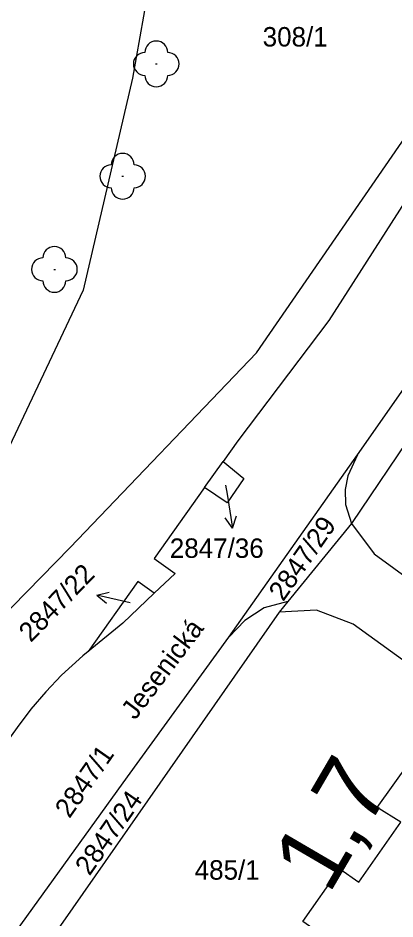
# Model space of a CAD drawing. Extents: x -558358 to -557517, y -1073786 to -1073189.
# Drawn here: x -558051.3 to -558018.3, y -1073345.8 to -1073267 of the extents above; entities that cross this region are included whole.
import ezdxf

# ---------------------------------------------------------------- set-up
doc = ezdxf.new("R2010")
doc.units = 0
for name, color, linetype in [('Drobná stavba - strom', 7, 'Continuous'), ('Hranice parcel', 7, 'Continuous'), ('Návěst místo trati', 7, 'Continuous'), ('Parcelní čísla', 7, 'Continuous'), ('Pop  PČ popisy', 7, 'Continuous'), ('Svazek obcí údolí Desné', 7, 'Continuous')]:
    doc.layers.add(name, color=color, linetype=linetype)

msp = doc.modelspace()

# ---------------------------------------------------------------- linework, layer by layer
at = {"layer": 'Drobná stavba - strom'}
for p, q in [((-558039.22, -1073271.013), (-558039.078, -1073271.013)), ((-558042.161, -1073280.838), (-558042.019, -1073280.838)), ((-558048.133, -1073288.982), (-558047.991, -1073288.982))]:
    msp.add_line(p, q, dxfattribs=at)
for centre, start, end in [((-558039.16, -1073270.011), 0, 180), ((-558040.16, -1073271.011), 90, 270), ((-558038.16, -1073271.011), 270, 90), ((-558039.16, -1073272.011), 180, 0), ((-558042.101, -1073279.836), 0, 180), ((-558043.101, -1073280.836), 90, 270), ((-558041.101, -1073280.836), 270, 90), ((-558042.101, -1073281.836), 180, 0), ((-558048.073, -1073287.98), 0, 180), ((-558049.073, -1073288.98), 90, 270), ((-558047.073, -1073288.98), 270, 90), ((-558048.073, -1073289.98), 180, 0)]:
    msp.add_arc(centre, 1, start, end, dxfattribs=at)
at = {"layer": 'Hranice parcel'}
for p, q in [((-557994.86, -1073270.9), (-558022.09, -1073311.21)), ((-558032.81, -1073321.13), (-558021.55, -1073305.19)), ((-558034.93, -1073308.06), (-558033.31, -1073305.78)), ((-558033.31, -1073305.78), (-558031.49, -1073307.27)), ((-558031.49, -1073307.27), (-558032.97, -1073309.39)), ((-558032.97, -1073309.39), (-558034.93, -1073308.06)), ((-558022.59, -1073309.53), (-558022.09, -1073311.21)), ((-558022.09, -1073311.21), (-558027.65, -1073318.03)), ((-558037.52, -1073315.57), (-558039.34, -1073317.31)), ((-558039.34, -1073317.31), (-558042.1, -1073319.93)), ((-558027.65, -1073318.03), (-558029.72, -1073318.58)), ((-558027.65, -1073318.03), (-558028.41, -1073318.97)), ((-558028.41, -1073318.97), (-558052.39, -1073353.27)), ((-558042.1, -1073319.93), (-558045.13, -1073322.4)), ((-558045.13, -1073322.4), (-558045.59, -1073322.77))]:
    msp.add_line(p, q, dxfattribs=at)
for points in [[(-557998.11, -1073217.81), (-557996.7, -1073222.28), (-557998.38, -1073242.39), (-558002.78, -1073257.43), (-558008.62, -1073269.37), (-558024.06, -1073293.44), (-558032.02, -1073303.96), (-558033.31, -1073305.78)], [(-558021.55, -1073305.19), (-558007.79, -1073285.56), (-557998.91, -1073272.25), (-557998.29, -1073271.45), (-557997.41, -1073270.82), (-557995.96, -1073270.7)], [(-558021.55, -1073305.19), (-558022.41, -1073307.04), (-558022.62, -1073308.24), (-558022.59, -1073309.53)], [(-558034.93, -1073308.06), (-558039.34, -1073314.26), (-558037.52, -1073315.57)], [(-558022.09, -1073311.21), (-558020.08, -1073313.87), (-558000.41, -1073328.2), (-557993.92, -1073334.5), (-557986.04, -1073343.93), (-557967.1, -1073369.2), (-557918.24, -1073434.51), (-557914.64, -1073436.24), (-557909.55, -1073436.22), (-557905.05, -1073434.1), (-557902.57, -1073430.65), (-557891.22, -1073414.37), (-557877.97, -1073395.43)], [(-558039.34, -1073317.31), (-558040.78, -1073316.28), (-558045.13, -1073322.4)], [(-558029.72, -1073318.58), (-558031.41, -1073319.68), (-558032.81, -1073321.13)], [(-558012.98, -1073326.49), (-558021.93, -1073320.01), (-558025.13, -1073318.78), (-558028.41, -1073318.97)], [(-558055.56, -1073352.56), (-558041.67, -1073333.36), (-558032.81, -1073321.13)], [(-558045.59, -1073322.77), (-558047.44, -1073324.48), (-558048.82, -1073325.91), (-558050.13, -1073327.44), (-558051.32, -1073329.04), (-558056.02, -1073335.51), (-558057.5, -1073338.08), (-558058.16, -1073339.69), (-558058.43, -1073340.61)], [(-558017.77, -1073337.32), (-558019.82, -1073336.05), (-558012.98, -1073326.49)], [(-558034.47, -1073361.24), (-558036.19, -1073360.05), (-558033.38, -1073356.04), (-558031.73, -1073357.2), (-558024.67, -1073347.17), (-558026.34, -1073346.01), (-558023.11, -1073341.4), (-558021.44, -1073342.56), (-558017.77, -1073337.32)]]:
    msp.add_lwpolyline(points, dxfattribs=at)
at = {"layer": 'Pop  PČ popisy'}
for p, q in [((-558033.09, -1073307.84), (-558032.96, -1073308.65)), ((-558032.96, -1073308.65), (-558032.491, -1073311.614)), ((-558032.491, -1073311.614), (-558033.142, -1073310.703)), ((-558032.491, -1073311.614), (-558032.153, -1073310.547)), ((-558044.374, -1073317.465), (-558043.286, -1073317.202)), ((-558041.45, -1073318.14), (-558044.374, -1073317.465)), ((-558044.374, -1073317.465), (-558043.511, -1073318.178))]:
    msp.add_line(p, q, dxfattribs=at)
at = {"layer": 'Svazek obcí údolí Desné'}
for points in [[(-558025.68, -1073189.916), (-558032.09, -1073212.63), (-558035.15, -1073249.33), (-558039.97, -1073265.01), (-558041.24, -1073272.26), (-558045.55, -1073290.79), (-558055.77, -1073312.33), (-558066.64, -1073329.29), (-558067.37, -1073328.67), (-558071.91, -1073335.47), (-558071.45, -1073339.78), (-558072.38, -1073341.74), (-558078.52, -1073350.81)], [(-558066.74, -1073350.64), (-558065.9, -1073348.86), (-558061.08, -1073328.44), (-558060.65, -1073327.54), (-558046.7, -1073313.29), (-558030.4, -1073296.27), (-558015.33, -1073274.48), (-558010.02, -1073266.4), (-558006.82, -1073259.79), (-558003.58, -1073251.39), (-558001.93, -1073245.63), (-558000.3, -1073233.47), (-558000.14, -1073230.76), (-558000.21, -1073228.76), (-558000.67, -1073225.31), (-558001.93, -1073222.03), (-558003.18, -1073219.55), (-558003.41, -1073218.32), (-558003.28, -1073217.31), (-558002.8, -1073216.38), (-558000.9, -1073214.81), (-557999.34, -1073213.91), (-558005.3, -1073194.99), (-558007.236, -1073189.964)]]:
    msp.add_lwpolyline(points, dxfattribs=at)

# ---------------------------------------------------------------- texts
at = {"layer": 'Návěst místo trati'}
msp.add_text('1,7', height=6, rotation=59.70509, dxfattribs=at).set_placement((-558024.055, -1073343.72))
at = {"layer": 'Parcelní čísla'}
for s, p in [('308/1', (-558029.848, -1073269.489)), ('2847/36', (-558037.975, -1073314.209)), ('485/1', (-558035.798, -1073342.35))]:
    msp.add_text(s, height=1.7, dxfattribs=at).set_placement(p)
for s, rotation, p in [('2847/29', 55, (-558028.055, -1073318.09)), ('2847/22', 46, (-558050.135, -1073321.67)), ('2847/1', 55, (-558046.758, -1073337.061)), ('2847/24', 55, (-558044.997, -1073342.081))]:
    msp.add_text(s, height=1.7, rotation=rotation, dxfattribs=at).set_placement(p)
at = {"layer": 'Pop  PČ popisy'}
msp.add_text('Jesenická', height=1.7, rotation=53, dxfattribs=at).set_placement((-558041.011, -1073328.461))

doc.saveas('drawing.dxf')
